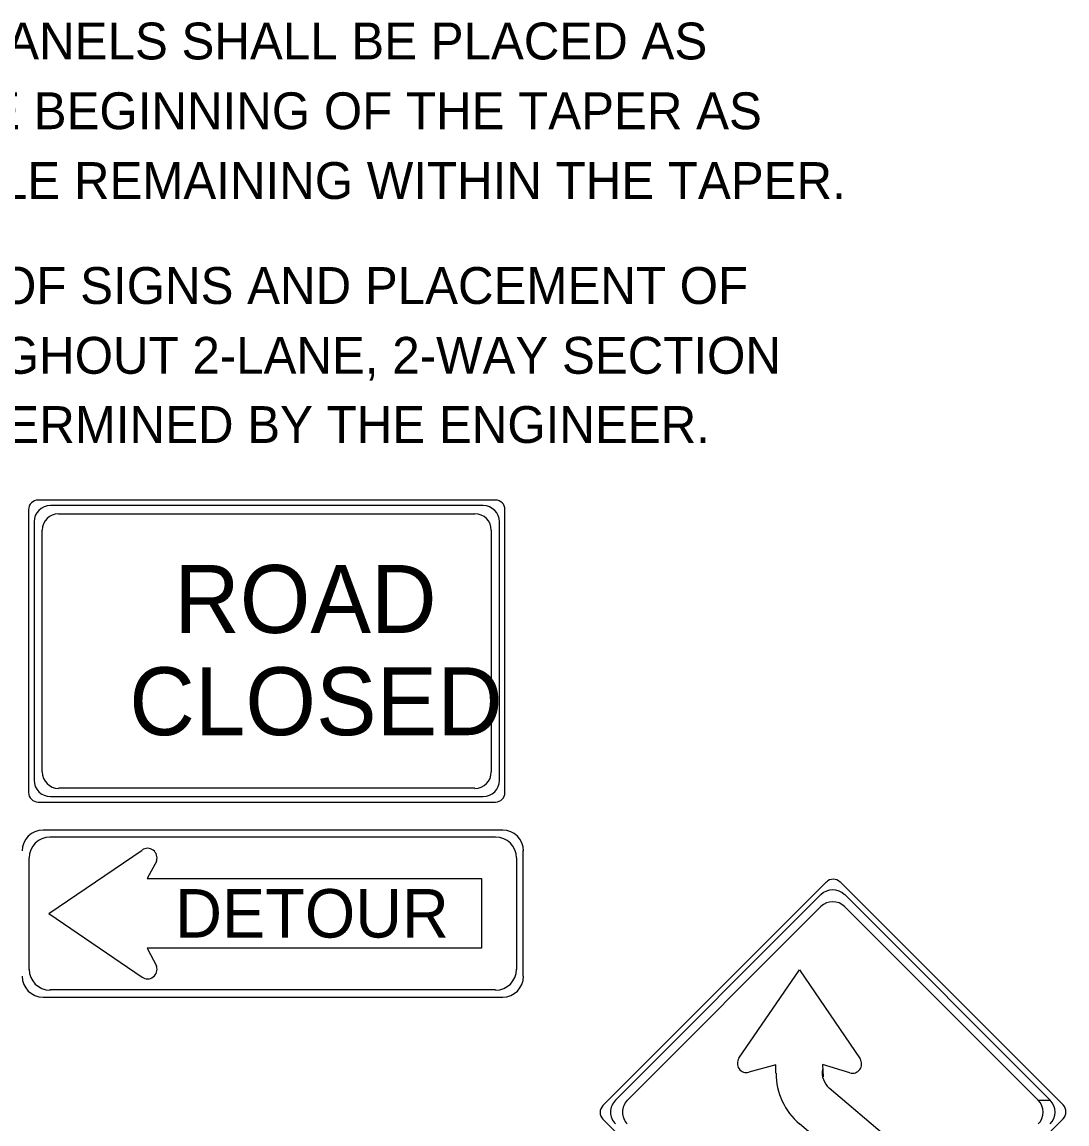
# Model space of a CAD drawing. Extents: x 1531.42 to 1538.58, y 1529.59 to 1539.57.
# Drawn here: x 1536.313 to 1538.015, y 1534.134 to 1535.928 of the extents above; entities that cross this region are included whole.
import ezdxf

# ---------------------------------------------------------------- set-up
doc = ezdxf.new("R2010")
doc.units = 0
doc.layers.add('DETL-LINE', color=7, linetype='Continuous')
doc.layers.add('DETL-NOTE', color=7, linetype='Continuous')

msp = doc.modelspace()

# ---------------------------------------------------------------- linework, layer by layer
at = {"layer": 'DETL-LINE'}
for p, q in [((1537.0837, 1535.1494), (1536.339, 1535.1494)), ((1536.3234, 1535.1338), (1536.3234, 1534.6734)), ((1537.0637, 1535.1405), (1536.359, 1535.1405)), ((1536.3724, 1535.1271), (1537.0503, 1535.1271)), ((1537.0993, 1534.6734), (1537.0993, 1535.1338)), ((1536.3323, 1535.1138), (1536.3323, 1534.6934)), ((1537.0904, 1534.6934), (1537.0904, 1535.1138)), ((1536.3457, 1534.7067), (1536.3457, 1535.1005)), ((1537.077, 1535.1005), (1537.077, 1534.7067)), ((1537.0503, 1534.6801), (1536.3724, 1534.6801)), ((1536.359, 1534.6667), (1537.0637, 1534.6667)), ((1536.339, 1534.6578), (1537.0837, 1534.6578)), ((1537.0956, 1534.6121), (1536.3471, 1534.6121)), ((1536.358, 1534.6013), (1537.0838, 1534.6013)), ((1536.3562, 1534.4761), (1536.5086, 1534.5795)), ((1537.1291, 1534.3745), (1537.1291, 1534.5786)), ((1536.3244, 1534.3853), (1536.3244, 1534.5668)), ((1536.5322, 1534.5623), (1536.5168, 1534.5332)), ((1537.1182, 1534.5668), (1537.1182, 1534.3853)), ((1536.5168, 1534.5332), (1537.0611, 1534.5332)), ((1537.0611, 1534.5332), (1537.0611, 1534.4198)), ((1537.6228, 1534.5277), (1537.2588, 1534.1639)), ((1538.0083, 1534.1645), (1537.6452, 1534.5277)), ((1537.6139, 1534.5071), (1537.2792, 1534.1722)), ((1537.9873, 1534.1722), (1537.6526, 1534.5071)), ((1537.2987, 1534.1724), (1537.6139, 1534.4875)), ((1537.6524, 1534.4875), (1537.9678, 1534.1722)), ((1537.6524, 1534.4875), (1537.6524, 1534.4875)), ((1536.3562, 1534.4761), (1536.5086, 1534.3727)), ((1536.5168, 1534.4198), (1536.5322, 1534.3899)), ((1537.0611, 1534.4198), (1536.5168, 1534.4198)), ((1537.4802, 1534.2405), (1537.5787, 1534.3847)), ((1537.5787, 1534.3847), (1537.6777, 1534.2395)), ((1536.3471, 1534.34), (1537.0956, 1534.34)), ((1537.0838, 1534.3518), (1536.358, 1534.3518)), ((1537.4803, 1534.2405), (1537.4802, 1534.2405)), ((1537.5406, 1534.2299), (1537.4965, 1534.2177)), ((1537.5406, 1534.2161), (1537.5406, 1534.2299)), ((1537.661, 1534.2166), (1537.6163, 1534.2303)), ((1537.6163, 1534.2303), (1537.6173, 1534.2106)), ((1537.6275, 1534.1923), (1537.7244, 1534.1101)), ((1537.9678, 1534.1722), (1537.9873, 1534.1722)), ((1537.2588, 1534.1412), (1537.6219, 1533.7781)), ((1537.6443, 1533.7781), (1538.0083, 1534.1421)), ((1537.6752, 1534.0522), (1537.5787, 1534.1339))]:
    msp.add_line(p, q, dxfattribs=at)
for centre, radius, start, end in [((1536.339, 1535.1338), 0.0156, 90, 180), ((1537.0837, 1535.1338), 0.0156, 0, 90), ((1536.359, 1535.1138), 0.0267, 90, 180), ((1536.3724, 1535.1005), 0.0267, 90, 180), ((1537.0503, 1535.1005), 0.0267, 0, 90), ((1537.0637, 1535.1138), 0.0267, 0, 90), ((1536.3724, 1534.7067), 0.0267, 180, 270), ((1537.0503, 1534.7067), 0.0267, 270, 0), ((1536.359, 1534.6934), 0.0267, 180, 270), ((1537.0637, 1534.6934), 0.0267, 270, 0), ((1536.339, 1534.6734), 0.0156, 180, 270), ((1537.0837, 1534.6734), 0.0156, 270, 0), ((1536.347, 1534.5782), 0.034, 90, 180), ((1537.0955, 1534.5782), 0.034, 0, 90), ((1536.3584, 1534.5668), 0.034, 90, 180), ((1537.0841, 1534.5668), 0.034, 0, 90), ((1536.5171, 1534.5668), 0.0156, 342, 124.2603), ((1536.347, 1534.374), 0.034, 180, 270), ((1536.3584, 1534.3854), 0.034, 180, 270), ((1536.5171, 1534.3854), 0.0156, 235.7397, 18), ((1537.0841, 1534.3854), 0.034, 270, 0), ((1537.0955, 1534.374), 0.034, 270, 0), ((1537.4926, 1534.2321), 0.0149, 145.7397, 285.4896), ((1537.6652, 1534.231), 0.0149, 253.1024, 34.2603), ((1537.649, 1534.2163), 0.1083, 180, 229.6651), ((1537.6484, 1534.2168), 0.0325, 169.2549, 229.6651)]:
    msp.add_arc(centre, radius, start, end, dxfattribs=at)
for centre, major_axis, start_param, end_param in [((1537.6331, 1534.4875), (0.0273, 0), 0.785398, 2.356194), ((1537.6339, 1534.5163), (0.0159, 0), 0.785398, 2.356194), ((1537.6331, 1534.4682), (0.0273, 0), 0.785398, 2.356194), ((1537.2701, 1534.1524), (0.0159, 0), 2.356194, 3.926991), ((1537.2985, 1534.1529), (0.0273, 0), 2.356194, 3.926991), ((1537.3178, 1534.1529), (0.0273, 0), 2.356194, 3.926991), ((1537.9484, 1534.1529), (0.0273, 0), 5.497787, 7.068583), ((1537.9678, 1534.1529), (0.0273, 0), 5.497787, 7.068583), ((1537.997, 1534.1533), (0.0159, 0), 5.497787, 7.068583)]:
    msp.add_ellipse(centre, major_axis=major_axis, ratio=0.999977, start_param=start_param, end_param=end_param, dxfattribs=at)

# ---------------------------------------------------------------- texts
for s, height, p in [('ROAD', 0.11061, (1536.5606, 1534.9331)), ('CLOSED', 0.11061, (1536.4874, 1534.7666)), ('DETOUR', 0.07893, (1536.5622, 1534.4371))]:
    msp.add_text(s, height=height, dxfattribs=at).set_placement(p)
at = {"layer": 'DETL-NOTE'}
for s, p in [('THE ARROW PANELS SHALL BE PLACED AS', (1535.721, 1535.8669)), ('CLOSE TO THE BEGINNING OF THE TAPER AS', (1535.721, 1535.7533)), ('POSSIBLE WHILE REMAINING WITHIN THE TAPER.', (1535.7017, 1535.6397)), ('THE NUMBER OF SIGNS AND PLACEMENT OF', (1535.721, 1535.4688)), ('SIGNS THROUGHOUT 2-LANE, 2-WAY SECTION', (1535.721, 1535.3551)), ('SHALL BE DETERMINED BY THE ENGINEER.', (1535.721, 1535.2424))]:
    msp.add_text(s, height=0.06, dxfattribs=at).set_placement(p)

doc.saveas('drawing.dxf')
